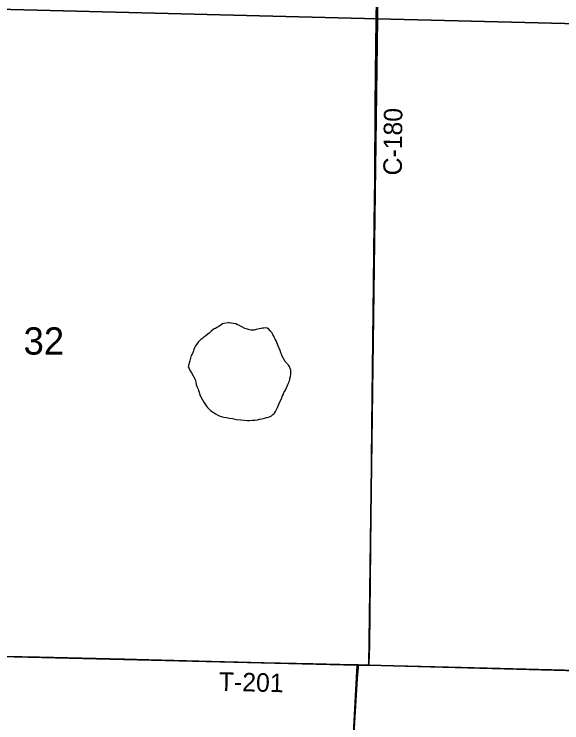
# Model space of a CAD drawing. Extents: x 1587405 to 1714697, y 1028970 to 1155083.
# Drawn here: x 1658486 to 1662922, y 1091803 to 1097544 of the extents above; entities that cross this region are included whole.
import ezdxf

# ---------------------------------------------------------------- set-up
doc = ezdxf.new("R2010")
doc.units = 0
for name, color, linetype in [('GM_X_County_Road', 7, 'Continuous'), ('GM_X_County_Road_Text', 7, 'Continuous'), ('GM_X_Minor_Lake', 7, 'Continuous'), ('GM_X_Section', 7, 'Continuous'), ('GM_X_Section_Text', 7, 'Continuous'), ('GM_X_Township_Road', 7, 'Continuous'), ('GM_X_Township_Road_Text', 7, 'Continuous')]:
    doc.layers.add(name, color=color, linetype=linetype)

msp = doc.modelspace()

# ---------------------------------------------------------------- linework, layer by layer
at = {"layer": 'GM_X_County_Road'}
for points in [[(1661355.2, 1092272.3), (1661359.2, 1092291.5), (1661362.5, 1092313.6), (1661363.6, 1092324.6), (1661365, 1092351.2), (1661367.3, 1092428), (1661368.8, 1092686.9), (1661374.3, 1093212.3), (1661376.5, 1093491.2), (1661376.7, 1093556.6), (1661380.1, 1093753.4), (1661380.7, 1093917.4), (1661383.9, 1094212.8), (1661386.4, 1094442.6), (1661396.4, 1095361.9), (1661398.8, 1095608.1), (1661402.1, 1095853.2), (1661406, 1096213.9), (1661410.6, 1096805), (1661416, 1097297.2), (1661420.5, 1097674.6)], [(1661130.2, 1089695), (1661151.7, 1090128.2), (1661202.5, 1091045.7), (1661224.1, 1091406), (1661240.2, 1091717.4), (1661265.8, 1092159.8), (1661268.6, 1092195.2), (1661273.6, 1092249.1), (1661276, 1092274.7)], [(1661276, 1092274.7), (1661355.2, 1092272.3)]]:
    msp.add_lwpolyline(points, dxfattribs=at)
at = {"layer": 'GM_X_Minor_Lake'}
for points in [[(1660681.1, 1094731.1), (1660658, 1094774.7), (1660650.2, 1094790.8), (1660646.3, 1094800.9), (1660640.5, 1094819.1), (1660622.9, 1094861.5), (1660619, 1094871.6), (1660613.1, 1094883.7), (1660607.2, 1094897.9), (1660601.3, 1094910), (1660595.4, 1094922.1), (1660589.6, 1094934.3), (1660581.7, 1094948.4), (1660573.8, 1094964.6), (1660559.9, 1094978.9), (1660550, 1094991), (1660534, 1095001.3), (1660519.9, 1095003.5), (1660507.8, 1095001.6), (1660497.7, 1094999.8), (1660485.6, 1094997.9), (1660471.5, 1094994.1), (1660459.4, 1094992.2), (1660447.2, 1094988.4), (1660431.1, 1094984.6), (1660415, 1094984.8), (1660404.9, 1094984.9), (1660390.8, 1094987.1), (1660374.8, 1094991.3), (1660354.7, 1094997.6), (1660334.7, 1095007.9), (1660324.7, 1095014.1), (1660306.7, 1095024.4), (1660294.7, 1095028.5), (1660280.6, 1095034.8), (1660260.6, 1095039), (1660242.4, 1095041.3), (1660228.4, 1095043.5), (1660218.3, 1095043.6), (1660184, 1095038), (1660173.9, 1095034.1), (1660161.7, 1095026.3), (1660143.4, 1095014.4), (1660127.2, 1095004.6), (1660117, 1094998.7), (1660106.9, 1094994.8), (1660094.7, 1094986.9), (1660082.5, 1094975.1), (1660064.2, 1094959.2), (1660054, 1094951.3), (1660037.7, 1094939.5), (1660023.5, 1094927.6), (1660013.3, 1094919.7), (1659999.1, 1094907.8), (1659984.8, 1094896), (1659976.6, 1094886), (1659964.4, 1094870.1), (1659954.1, 1094856.2), (1659947.9, 1094840.2), (1659941.7, 1094828.2), (1659937.5, 1094816.2), (1659929.2, 1094794.2), (1659920.9, 1094778.3), (1659914.6, 1094758.3), (1659909, 1094734.5)], [(1659909, 1094734.5), (1659895.3, 1094687.8), (1659903.3, 1094673.7), (1659911.3, 1094655.6), (1659921.3, 1094639.5), (1659951.3, 1094583.2), (1659957.3, 1094563.1), (1659961.2, 1094543.1), (1659969.2, 1094523), (1659975.2, 1094504.9), (1659979.2, 1094494.9), (1659983.2, 1094480.8), (1659989.1, 1094458.7), (1659999.1, 1094442.6), (1660011.1, 1094420.5), (1660023.1, 1094400.4), (1660033.1, 1094384.3), (1660043.1, 1094368.2), (1660053.1, 1094356.2), (1660069.1, 1094340.1), (1660079.2, 1094330), (1660093.2, 1094321.9), (1660105.2, 1094313.9), (1660123.2, 1094303.8), (1660141.3, 1094293.7), (1660163.3, 1094285.6), (1660185.4, 1094279.5), (1660205.5, 1094275.4), (1660227.5, 1094271.3), (1660253.6, 1094267.2), (1660285.7, 1094261.1), (1660321.8, 1094257), (1660349.9, 1094254.9), (1660374, 1094252.8), (1660392, 1094252.8), (1660416.1, 1094254.7), (1660434.2, 1094254.6), (1660456.3, 1094256.6), (1660474.3, 1094262.5), (1660492.4, 1094266.5), (1660512.5, 1094270.4), (1660530.6, 1094276.4), (1660546.6, 1094280.3), (1660558.7, 1094284.3), (1660570.7, 1094290.3), (1660580.8, 1094300.3), (1660594.9, 1094312.3), (1660602.9, 1094324.3), (1660611, 1094342.3), (1660619, 1094356.4), (1660625.1, 1094370.4), (1660631.2, 1094390.4), (1660653.3, 1094436.5), (1660657.4, 1094446.6), (1660665.4, 1094460.6), (1660671.5, 1094478.6), (1660679.6, 1094490.6), (1660685.6, 1094504.6), (1660691.7, 1094516.7), (1660697.7, 1094530.7), (1660703.8, 1094544.7), (1660709.8, 1094558.8), (1660713.9, 1094570.8), (1660717.9, 1094580.8), (1660719.9, 1094592.8), (1660724, 1094608.9), (1660726, 1094624.9), (1660726.1, 1094641), (1660728.1, 1094651), (1660726.1, 1094661), (1660722.1, 1094673.1), (1660720.1, 1094683.1), (1660710.1, 1094697.2), (1660681.1, 1094731.1)]]:
    msp.add_lwpolyline(points, dxfattribs=at)
at = {"layer": 'GM_X_Section'}
for points in [[(1656161.5, 1102928.9), (1661485.6, 1102806.5), (1661429.4, 1097506), (1656123.9, 1097642.2)], [(1661485.6, 1102806.5), (1666847.1, 1102659.7), (1666741, 1097373.7), (1661429.4, 1097506)], [(1661429.4, 1097506), (1661358.4, 1092269.9), (1661264.4, 1092271), (1656039.3, 1092397.9), (1656123.9, 1097642.2)], [(1666741, 1097373.7), (1666653.8, 1092126.1), (1666555.8, 1092129.2), (1661358.4, 1092269.9), (1661429.4, 1097506)], [(1655871.3, 1092400.1), (1656039.3, 1092397.9), (1661264.4, 1092271), (1660988.4, 1087141.1), (1655606.5, 1087308.4)], [(1661264.4, 1092271), (1661358.4, 1092269.9), (1666555.8, 1092129.2), (1666401.8, 1086987.9), (1660988.4, 1087141.1)]]:
    msp.add_lwpolyline(points, close=True, dxfattribs=at)
at = {"layer": 'GM_X_Township_Road'}
for points in [[(1657378.8, 1092363.7), (1657657.6, 1092357.1), (1657985.7, 1092350.6), (1658691, 1092336.2), (1659379.9, 1092320.3), (1659576.7, 1092314.9), (1660085.2, 1092303), (1660511.6, 1092292.6), (1660905.3, 1092283.3), (1661233.4, 1092276), (1661276, 1092274.7)], [(1661355.2, 1092272.3), (1661561.3, 1092266.1), (1662004.2, 1092256), (1663152.4, 1092227.2), (1663513.2, 1092218.4), (1663939.6, 1092206.5), (1664008.6, 1092205.3)]]:
    msp.add_lwpolyline(points, dxfattribs=at)

# ---------------------------------------------------------------- texts
at = {"layer": 'GM_X_County_Road_Text'}
msp.add_text('C-180', height=150, rotation=89.44765, dxfattribs=at).set_placement((1661625.5, 1096237.3))
at = {"layer": 'GM_X_Section_Text'}
msp.add_text('32', height=221, rotation=0.00001, dxfattribs=at).set_placement((1658562.2, 1094786))
at = {"layer": 'GM_X_Township_Road_Text'}
msp.add_text('T-201', height=150, rotation=358.59569, dxfattribs=at).set_placement((1660142.6, 1092063.2))

doc.saveas('drawing.dxf')
